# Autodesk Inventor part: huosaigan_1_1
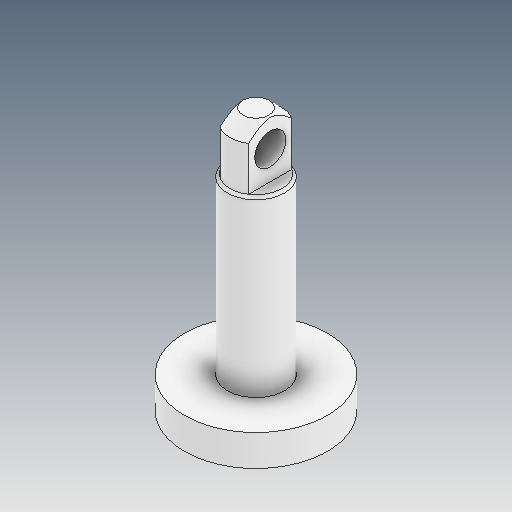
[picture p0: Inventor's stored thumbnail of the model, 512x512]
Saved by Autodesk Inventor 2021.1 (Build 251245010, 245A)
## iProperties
Created: 2021-05
Part Number: huosaigan_1_1
Material: Ogólny
Document SubType Name: Modeling
Designer: user
Density: 1 g/cm^3
Appearance: Domyślna
Author: user
Revision Number: ÈÎºÎ
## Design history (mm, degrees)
feature "ÊäÈë1"
node "Bryła1"
